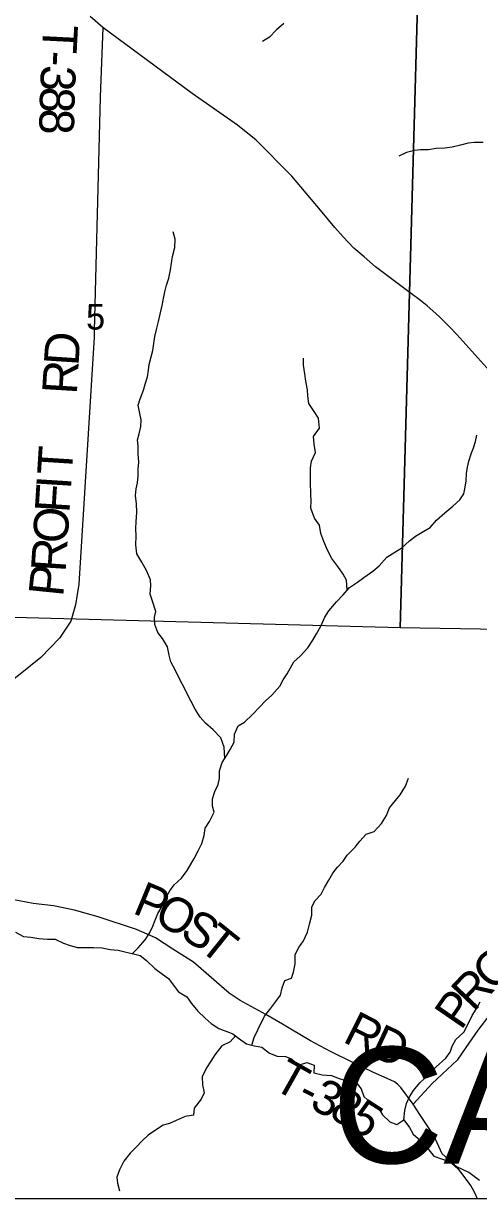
# Model space of a CAD drawing. Extents: x -3.6 to 34, y 0 to 32.8.
# Drawn here: x -0.41 to 0.333, y 26.043 to 27.961 of the extents above; entities that cross this region are included whole.
import ezdxf

# ---------------------------------------------------------------- set-up
doc = ezdxf.new("R2010")
doc.units = 0
for name, color, linetype in [('GM_X_Corporation', 7, 'Continuous'), ('GM_X_County_Text', 7, 'Continuous'), ('GM_X_Minor_River', 7, 'Continuous'), ('GM_X_Section_Text', 7, 'Continuous'), ('GM_X_State_Route', 7, 'Continuous'), ('GM_X_Township_Road', 7, 'Continuous'), ('GM_X_Township_Road_Text', 7, 'Continuous'), ('SH_Data', 7, 'Continuous')]:
    doc.layers.add(name, color=color, linetype=linetype)

msp = doc.modelspace()

# ---------------------------------------------------------------- linework, layer by layer
at = {"layer": 'GM_X_Corporation'}
for points in [[(3.1705, 28.9337), (3.1705, 32.8429), (-3.6295, 32.8429), (-3.6295, 26.0429), (2.3706, 26.0429), (2.3712, 26.0804), (2.3716, 26.1248), (2.3732, 26.2253), (2.3789, 26.6097), (2.3911, 27.5117), (2.3952, 27.9336), (2.3997, 28.282), (2.4082, 28.9473), (2.5416, 28.945), (2.5837, 28.9442), (2.8343, 28.9397)], [(-0.7925, 28.0131), (0.2336, 27.9902), (0.2053, 26.9746), (-0.8131, 27.0015)], [(1.398, 27.966), (1.386, 26.9549), (0.2053, 26.9746), (0.2336, 27.9902)]]:
    msp.add_lwpolyline(points, close=True, dxfattribs=at)
msp.add_lwpolyline([(-2.8635, 26.0429), (2.3706, 26.0429), (2.3712, 26.0804), (2.3716, 26.1248), (2.3732, 26.2253), (2.3789, 26.6097), (2.3911, 27.5117), (2.3952, 27.9336), (2.3997, 28.282), (2.4082, 28.9473), (2.5416, 28.945), (2.5837, 28.9442), (2.8343, 28.9397), (3.1705, 28.9337), (3.1705, 30.458), (3.0419, 30.4594), (1.7819, 30.4857), (1.2437, 30.4948), (0.4055, 30.5105), (0.3556, 30.5115), (0.2578, 30.5133), (0.2583, 30.5905), (-0.398, 30.5946), (-0.453, 30.5952)], dxfattribs=at)
at = {"layer": 'GM_X_Minor_River'}
for points in [[(0.0153, 27.961), (0.0033, 27.9502), (-0.0082, 27.9386), (-0.0198, 27.9313)], [(0.2515, 27.7547), (0.2386, 27.7545), (0.2288, 27.7536), (0.2156, 27.75), (0.2032, 27.7441)], [(0.341, 27.7663), (0.3266, 27.7665), (0.3164, 27.7652), (0.3036, 27.762), (0.29, 27.7591), (0.2783, 27.7574), (0.2643, 27.7565), (0.2515, 27.7547)], [(-0.0811, 26.7613), (-0.0823, 26.7795), (-0.0878, 26.795), (-0.1005, 26.8081), (-0.1128, 26.8189), (-0.1212, 26.8287), (-0.1298, 26.8415), (-0.136, 26.8539), (-0.1504, 26.8818), (-0.1558, 26.892), (-0.1621, 26.9056), (-0.1695, 26.9187), (-0.1723, 26.9297), (-0.1751, 26.9433), (-0.1829, 26.9569), (-0.1906, 26.9667), (-0.1957, 26.9799), (-0.1963, 26.9916), (-0.1937, 27.0012), (-0.1993, 27.0178), (-0.2029, 27.0291), (-0.2023, 27.0432), (-0.2024, 27.0527), (-0.2087, 27.0666), (-0.2165, 27.0813), (-0.225, 27.0953), (-0.2267, 27.11), (-0.2262, 27.1241), (-0.2264, 27.1363), (-0.2258, 27.1473), (-0.2249, 27.1632), (-0.2254, 27.1769), (-0.2272, 27.1906), (-0.2258, 27.2012), (-0.2241, 27.2111), (-0.2227, 27.2225), (-0.2225, 27.2335), (-0.2219, 27.2449), (-0.2225, 27.2582), (-0.223, 27.2711), (-0.2236, 27.281), (-0.2211, 27.2909), (-0.2182, 27.3031), (-0.2176, 27.3141), (-0.22, 27.3243), (-0.2225, 27.338), (-0.2196, 27.3483), (-0.2142, 27.3624), (-0.2113, 27.3719), (-0.2073, 27.3841), (-0.2059, 27.3948), (-0.2046, 27.4043), (-0.2017, 27.4169), (-0.1988, 27.4268), (-0.1971, 27.4382), (-0.1958, 27.45), (-0.1922, 27.4633), (-0.1897, 27.4744), (-0.1869, 27.4862), (-0.1833, 27.5007), (-0.1812, 27.5121), (-0.1791, 27.5227), (-0.1762, 27.5334), (-0.1726, 27.5452), (-0.1701, 27.5586), (-0.1667, 27.5806), (-0.1631, 27.5951), (-0.1622, 27.6088), (-0.1658, 27.6209)], [(0.1187, 27.0359), (0.1177, 27.0522), (0.1119, 27.062), (0.1034, 27.0744), (0.0937, 27.0876), (0.0863, 27.1011), (0.0808, 27.1155), (0.0757, 27.1283), (0.0732, 27.142), (0.0651, 27.1536), (0.0592, 27.1698), (0.0598, 27.1816), (0.0593, 27.1922), (0.059, 27.2128), (0.0586, 27.2355), (0.0604, 27.2462), (0.067, 27.2607), (0.0649, 27.274), (0.0639, 27.2865), (0.0732, 27.3003), (0.0718, 27.3166), (0.0645, 27.3275), (0.056, 27.3403), (0.0546, 27.3532), (0.0537, 27.363), (0.0509, 27.3767), (0.0496, 27.3892), (0.0471, 27.4032), (0.0473, 27.4146)], [(-0.232, 26.4428), (-0.2229, 26.4519), (-0.2113, 26.4653), (-0.2043, 26.4757), (-0.1988, 26.4876), (-0.1951, 26.4971), (-0.1904, 26.5082), (-0.1834, 26.5201), (-0.179, 26.5308), (-0.1709, 26.545), (-0.1638, 26.5546), (-0.1519, 26.5658), (-0.1426, 26.578), (-0.1374, 26.5876), (-0.1315, 26.598), (-0.1249, 26.6102), (-0.119, 26.6225), (-0.1147, 26.6354), (-0.1133, 26.6472), (-0.1063, 26.658), (-0.0986, 26.6737), (-0.1014, 26.6835), (-0.1011, 26.6953), (-0.0975, 26.7071), (-0.092, 26.7186), (-0.0899, 26.7289), (-0.0901, 26.741), (-0.0854, 26.7544), (-0.078, 26.7663), (-0.0724, 26.7759), (-0.0662, 26.7877), (-0.0652, 26.8007), (-0.0594, 26.8144), (-0.0492, 26.8203), (-0.0358, 26.833), (-0.0246, 26.845), (-0.0149, 26.8554), (-0.0045, 26.8643), (0.0086, 26.8789), (0.0141, 26.8896), (0.0208, 26.8992), (0.0259, 26.9088), (0.0315, 26.9191), (0.0419, 26.928), (0.0546, 26.9415), (0.0624, 26.9542), (0.0686, 26.9645), (0.0756, 26.9772), (0.0822, 26.9917), (0.0885, 27.002), (0.1012, 27.0167), (0.112, 27.0282), (0.1224, 27.0402), (0.1355, 27.0491), (0.146, 27.0565), (0.1606, 27.0666), (0.1707, 27.0755), (0.1837, 27.0897), (0.1965, 27.0979), (0.2081, 27.1049), (0.2204, 27.1161), (0.2305, 27.1238), (0.244, 27.132), (0.2542, 27.1382), (0.2646, 27.1502), (0.278, 27.1618), (0.2915, 27.173), (0.3027, 27.1834), (0.3094, 27.193), (0.3115, 27.204), (0.3128, 27.2143), (0.3138, 27.2265), (0.3151, 27.2368), (0.3173, 27.2463), (0.3213, 27.2585), (0.3249, 27.268), (0.3282, 27.2783), (0.3303, 27.2886)], [(-0.0371, 26.2929), (-0.0334, 26.3059), (-0.0272, 26.3181), (-0.0165, 26.3403), (-0.0076, 26.3515), (0.0024, 26.3642), (0.0095, 26.3749), (0.0127, 26.3867), (0.0167, 26.3989), (0.0276, 26.4025), (0.0309, 26.4124), (0.0337, 26.4258), (0.0335, 26.441), (0.0397, 26.4528), (0.0471, 26.4636), (0.0538, 26.4777), (0.057, 26.4907), (0.0609, 26.5056), (0.0611, 26.5192), (0.0666, 26.5292), (0.0763, 26.5396), (0.0818, 26.5503), (0.0885, 26.5626), (0.0951, 26.5741), (0.1029, 26.5837), (0.1122, 26.5937), (0.1189, 26.6033), (0.1316, 26.6164), (0.1394, 26.626), (0.1498, 26.6376), (0.163, 26.642), (0.1745, 26.6551), (0.183, 26.6681), (0.1878, 26.6807), (0.1978, 26.6923), (0.2053, 26.7019), (0.2141, 26.716), (0.2189, 26.729)], [(-0.423, 26.4777), (-0.4101, 26.4707), (-0.3983, 26.4693), (-0.385, 26.4672), (-0.371, 26.4663), (-0.3582, 26.4661), (-0.3448, 26.4595), (-0.3353, 26.4562), (-0.3224, 26.4526), (-0.3084, 26.4525), (-0.2955, 26.4527), (-0.2815, 26.4521), (-0.2686, 26.4493), (-0.2553, 26.4483), (-0.2424, 26.4451), (-0.2326, 26.443), (-0.2193, 26.4394), (-0.2089, 26.4316), (-0.1955, 26.4185), (-0.1829, 26.4088), (-0.1733, 26.4017), (-0.1656, 26.3916), (-0.1567, 26.3803), (-0.143, 26.3718), (-0.1356, 26.3609), (-0.1252, 26.3485), (-0.1133, 26.3373), (-0.1034, 26.3284), (-0.0908, 26.3202), (-0.0778, 26.3155), (-0.0683, 26.3114), (-0.0587, 26.3047), (-0.0457, 26.2951), (-0.0328, 26.2918), (-0.0207, 26.2898), (-0.0081, 26.2801), (0.0045, 26.2753), (0.0178, 26.2744), (0.028, 26.2711), (0.0391, 26.2607), (0.0527, 26.2647), (0.0645, 26.2607), (0.0643, 26.2478), (0.078, 26.2446), (0.0928, 26.2436), (0.1057, 26.2385), (0.1198, 26.2346), (0.133, 26.2329), (0.1415, 26.2216), (0.1459, 26.2091), (0.1581, 26.1987), (0.17, 26.1902), (0.1762, 26.1796), (0.1881, 26.168), (0.1999, 26.1637), (0.2115, 26.171), (0.2204, 26.1587), (0.2266, 26.1481), (0.2385, 26.1373), (0.2504, 26.1246), (0.2604, 26.1122), (0.273, 26.1078), (0.2863, 26.1035), (0.2993, 26.0919), (0.3105, 26.0769), (0.3206, 26.0634), (0.3272, 26.0517), (0.331, 26.0429)], [(0.2115, 26.171), (0.2128, 26.1866), (0.2156, 26.1981), (0.2204, 26.2088), (0.2271, 26.2191), (0.2375, 26.2314), (0.2539, 26.2469), (0.2643, 26.258), (0.2796, 26.2719), (0.2871, 26.2816), (0.29, 26.2915), (0.2962, 26.3022), (0.3093, 26.3145), (0.317, 26.3291), (0.3229, 26.3417), (0.3292, 26.3521), (0.3358, 26.3639)], [(-0.0639, 26.3084), (-0.0727, 26.2988), (-0.0862, 26.2918), (-0.0977, 26.2772), (-0.104, 26.2672), (-0.111, 26.2561), (-0.118, 26.2416), (-0.1174, 26.2283), (-0.115, 26.2154), (-0.1201, 26.2051), (-0.1312, 26.1905), (-0.1326, 26.1791), (-0.1458, 26.1766), (-0.1605, 26.1703), (-0.1717, 26.1652), (-0.1819, 26.1624), (-0.1947, 26.1542), (-0.2066, 26.1464), (-0.2163, 26.1368), (-0.226, 26.1264), (-0.2357, 26.1167), (-0.2461, 26.1037), (-0.2535, 26.0899), (-0.2575, 26.0777), (-0.2566, 26.0678), (-0.2534, 26.0553)]]:
    msp.add_lwpolyline(points, dxfattribs=at)
at = {"layer": 'GM_X_State_Route'}
msp.add_lwpolyline([(0.3515, 27.3935), (0.298, 27.453), (0.2866, 27.4651), (0.2797, 27.4719), (0.2693, 27.4819), (0.2585, 27.4918), (0.2491, 27.4997), (0.2384, 27.5084), (0.2235, 27.5196), (0.2066, 27.5324), (0.1652, 27.5636), (0.1463, 27.58), (0.1296, 27.5943), (0.1119, 27.6125), (0.0986, 27.6278), (0.0777, 27.6529), (0.0518, 27.6838), (0.0283, 27.7117), (-0.0299, 27.7702), (-0.0605, 27.7947), (-0.1344, 27.8465), (-0.2804, 27.954), (-0.3014, 27.972)], dxfattribs=at)
at = {"layer": 'GM_X_Township_Road'}
for points in [[(-0.2804, 27.954), (-0.2848, 27.8404), (-0.2946, 27.4589)], [(-0.2946, 27.4589), (-0.2948, 27.449), (-0.3199, 27.0458), (-0.3252, 27.0119), (-0.3326, 26.985), (-0.3514, 26.9576), (-0.3819, 26.9261), (-0.4155, 26.8987), (-0.4454, 26.8755), (-0.4537, 26.8403), (-0.459, 26.7861), (-0.4566, 26.7489), (-0.4555, 26.7158), (-0.4583, 26.6899), (-0.4632, 26.6669), (-0.4453, 26.6102), (-0.4465, 26.5849), (-0.4455, 26.5596), (-0.4495, 26.5346)], [(0.3347, 26.072), (0.3173, 26.0853), (0.298, 26.0947), (0.274, 26.1155), (0.26, 26.1456), (0.2372, 26.1798), (0.2263, 26.197), (0.2063, 26.2243), (0.201, 26.2294), (0.1958, 26.2334), (0.1842, 26.2385), (0.1619, 26.2483), (0.1267, 26.2652), (0.0915, 26.283), (0.0587, 26.3), (0.0266, 26.3194), (0.0128, 26.3275), (-0.0143, 26.3432), (-0.0561, 26.3663), (-0.0739, 26.3781), (-0.1321, 26.4288), (-0.1662, 26.4501), (-0.1944, 26.4683), (-0.2253, 26.482), (-0.2882, 26.5026), (-0.3265, 26.5134), (-0.3608, 26.5203), (-0.3941, 26.5242), (-0.4288, 26.5307)], [(0.352, 26.344), (0.3321, 26.3177), (0.3125, 26.2892), (0.2981, 26.2688), (0.2576, 26.2306), (0.2263, 26.197)]]:
    msp.add_lwpolyline(points, dxfattribs=at)
at = {"layer": 'SH_Data'}
msp.add_line((-3.6295, 26.0429), (3.1705, 26.0429), dxfattribs=at)

# ---------------------------------------------------------------- texts
at = {"layer": 'GM_X_County_Text'}
msp.add_text('CARROLL COUNTY', height=0.189394, rotation=359.4336, dxfattribs=at).set_placement((0.0928, 26.1015))
at = {"layer": 'GM_X_Section_Text'}
msp.add_text('5', height=0.0419, rotation=0, dxfattribs=at).set_placement((-0.3079, 27.4612))
at = {"layer": 'GM_X_Township_Road_Text'}
for s, rotation, p in [('T', 267.0845, (-0.3777, 27.9598)), ('-', 267.1819, (-0.3798, 27.9173)), ('3', 267.4613, (-0.381, 27.8937)), ('8', 268.0162, (-0.3826, 27.8581)), ('8', 268.9748, (-0.3838, 27.8221)), ('D', 86.227, (-0.3203, 27.401)), ('R', 86.5125, (-0.3231, 27.3545)), ('T', 86.3711, (-0.3312, 27.2226)), ('I', 86.3708, (-0.3327, 27.1993)), ('F', 86.3675, (-0.3351, 27.161)), ('O', 86.3688, (-0.3383, 27.1111)), ('R', 86.1916, (-0.3414, 27.0644)), ('P', 84.1743, (-0.3455, 27.024)), ('P', 337.4437, (-0.2337, 26.5093)), ('O', 330.5536, (-0.1999, 26.4954)), ('S', 327.1435, (-0.1571, 26.4713)), ('T', 321.1618, (-0.1262, 26.4514)), ('O', 43.8485, (0.3567, 26.3792)), ('R', 46.5374, (0.3251, 26.3459)), ('P', 55.4718, (0.3048, 26.3161)), ('R', 333.2342, (0.1095, 26.2996)), ('D', 334.9471, (0.1528, 26.2778)), ('T', 330.6317, (-0.0054, 26.2238)), ('-', 333.4312, (0.0343, 26.2016)), ('3', 333.4424, (0.0552, 26.1911)), ('8', 333.7554, (0.0868, 26.1753)), ('5', 327.3564, (0.1167, 26.1607))]:
    msp.add_text(s, height=0.0568, rotation=rotation, dxfattribs=at).set_placement(p)

doc.saveas('drawing.dxf')
